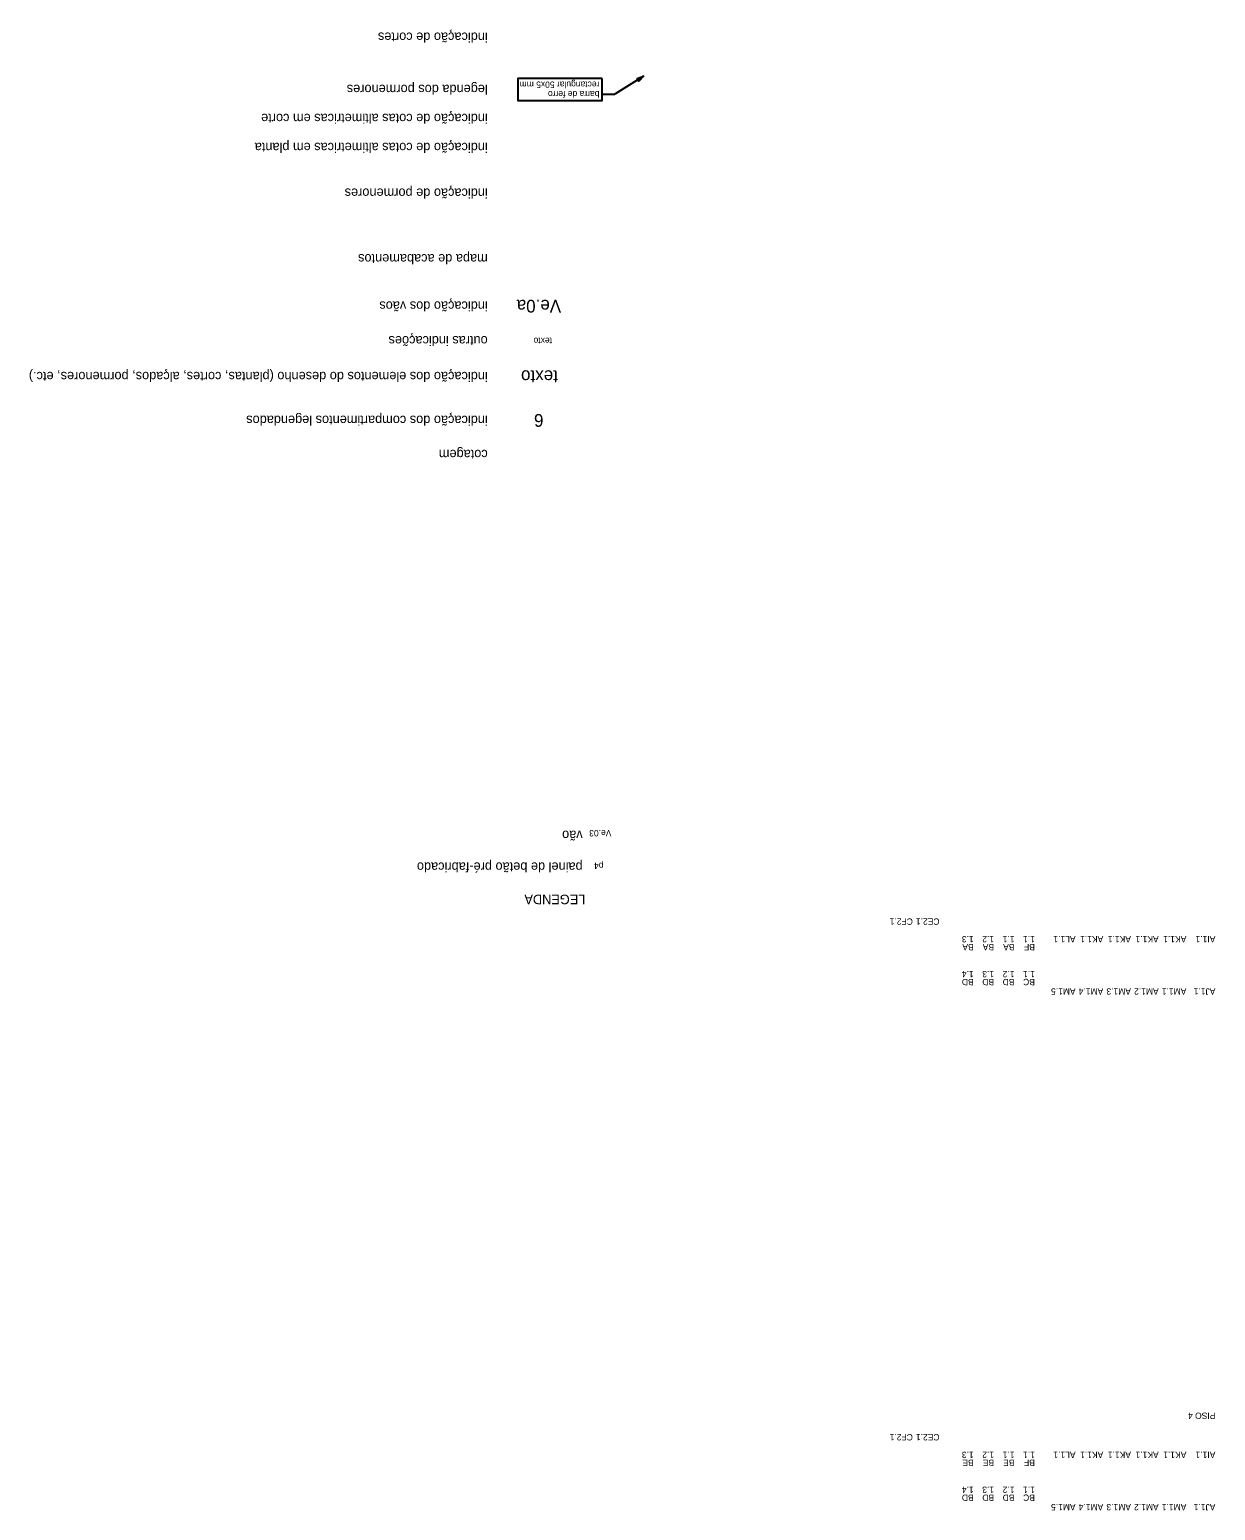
# Model space of a CAD drawing. Extents: x 1248 to 1356, y -443 to -224.
# Drawn here: x 1247.83 to 1285.17, y -327.86 to -281.23 of the extents above; entities that cross this region are included whole.
import ezdxf

# ---------------------------------------------------------------- set-up
doc = ezdxf.new("R2010")
doc.units = 0
doc.layers.add('Level 60', color=7, linetype='Continuous')

msp = doc.modelspace()

# ---------------------------------------------------------------- linework, layer by layer
at = {"layer": 'Level 60'}
for p, q in [((1267.157, -282.704), (1266.261, -283.268)), ((1265.86, -283.27), (1266.26, -283.27))]:
    msp.add_line(p, q, dxfattribs=at)
for points in [[(1265.86, -282.771), (1263.201, -282.771), (1263.201, -283.47), (1265.86, -283.47)], [(1266.961, -282.768), (1267.157, -282.704), (1267.015, -282.853)]]:
    msp.add_lwpolyline(points, close=True, dxfattribs=at)

# ---------------------------------------------------------------- texts
for s, height, p in [('indicação de cortes', 0.3, (1262.256, -281.326)), ('legenda dos pormenores', 0.3, (1262.256, -282.97)), ('rectangular 50x5 mm', 0.2, (1265.773, -282.868)), ('barra de ferro', 0.2, (1265.773, -283.168)), ('indicação de cotas altimetricas em corte', 0.3, (1262.256, -283.884)), ('indicação de cotas altimetricas em planta', 0.3, (1262.256, -284.798)), ('indicação de pormenores', 0.3, (1262.256, -286.236)), ('mapa de acabamentos', 0.3, (1262.256, -288.303)), ('indicação dos vãos', 0.3, (1262.256, -289.791)), ('Ve.0a', 0.4, (1264.567, -289.741)), ('outras indicações', 0.3, (1262.256, -290.883)), ('texto', 0.2, (1264.28, -290.933)), ('indicação dos elementos do desenho (plantas, cortes, alçados, pormenores, etc.)', 0.3, (1262.256, -292.01)), ('texto', 0.4, (1264.465, -291.961)), ('indicação dos compartimentos legendados', 0.3, (1262.256, -293.389)), ('6', 0.4, (1264.012, -293.339)), ('cotagem', 0.3, (1262.256, -294.464)), ('vão', 0.3, (1265.245, -306.455)), ('Ve.03', 0.2, (1266.151, -306.437)), ('painel de betão pré-fabricado', 0.3, (1265.245, -307.455)), ('p4', 0.2, (1265.902, -307.466)), ('LEGENDA', 0.3, (1265.329, -308.471)), ('CF2.1', 0.2, (1275.643, -309.219)), ('CE2.1', 0.2, (1276.483, -309.219)), ('1.3', 0.2, (1277.558, -309.774)), ('BA', 0.2, (1277.558, -310.024)), ('1.2', 0.2, (1278.201, -309.774)), ('BA', 0.2, (1278.201, -310.024)), ('1.1', 0.2, (1278.843, -309.774)), ('BA', 0.2, (1278.843, -310.024)), ('1.1', 0.2, (1279.485, -309.774)), ('BF', 0.2, (1279.485, -310.024)), ('AL1.1', 0.2, (1280.766, -309.774)), ('AK1.1', 0.2, (1281.638, -309.774)), ('AK1.1', 0.2, (1282.51, -309.774)), ('AK1.1', 0.2, (1283.383, -309.774)), ('AK1.1', 0.2, (1284.255, -309.774)), ('AI1.1', 0.2, (1285.169, -309.774)), ('1.4', 0.2, (1277.558, -310.871)), ('1.3', 0.2, (1278.201, -310.871)), ('1.2', 0.2, (1278.843, -310.871)), ('1.1', 0.2, (1279.485, -310.871)), ('BD', 0.2, (1277.558, -311.121)), ('BD', 0.2, (1278.201, -311.121)), ('BD', 0.2, (1278.843, -311.121)), ('BC', 0.2, (1279.485, -311.121)), ('AM1.5', 0.2, (1280.766, -311.418)), ('AM1.4', 0.2, (1281.638, -311.418)), ('AM1.3', 0.2, (1282.51, -311.418)), ('AM1.2', 0.2, (1283.383, -311.418)), ('AM1.1', 0.2, (1284.255, -311.418)), ('AJ1.1', 0.2, (1285.169, -311.418)), ('PISO 4', 0.2, (1285.169, -324.778)), ('CF2.1', 0.2, (1275.643, -325.454)), ('CE2.1', 0.2, (1276.483, -325.454)), ('1.3', 0.2, (1277.558, -326.01)), ('BE', 0.2, (1277.558, -326.26)), ('1.2', 0.2, (1278.201, -326.01)), ('BE', 0.2, (1278.201, -326.26)), ('1.1', 0.2, (1278.843, -326.01)), ('BE', 0.2, (1278.843, -326.26)), ('1.1', 0.2, (1279.485, -326.01)), ('BF', 0.2, (1279.485, -326.26)), ('AL1.1', 0.2, (1280.766, -326.01)), ('AK1.1', 0.2, (1281.638, -326.01)), ('AK1.1', 0.2, (1282.51, -326.01)), ('AK1.1', 0.2, (1283.383, -326.01)), ('AK1.1', 0.2, (1284.255, -326.01)), ('AI1.1', 0.2, (1285.169, -326.01)), ('1.4', 0.2, (1277.558, -327.107)), ('1.3', 0.2, (1278.201, -327.107)), ('1.2', 0.2, (1278.843, -327.107)), ('1.1', 0.2, (1279.485, -327.107)), ('BD', 0.2, (1277.558, -327.357)), ('BD', 0.2, (1278.201, -327.357)), ('BD', 0.2, (1278.843, -327.357)), ('BC', 0.2, (1279.485, -327.357)), ('AM1.5', 0.2, (1280.766, -327.654)), ('AM1.4', 0.2, (1281.638, -327.654)), ('AM1.3', 0.2, (1282.51, -327.654)), ('AM1.2', 0.2, (1283.383, -327.654)), ('AM1.1', 0.2, (1284.255, -327.654)), ('AJ1.1', 0.2, (1285.169, -327.654))]:
    msp.add_text(s, height=height, rotation=180, dxfattribs=at).set_placement(p)

doc.saveas('drawing.dxf')
